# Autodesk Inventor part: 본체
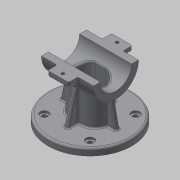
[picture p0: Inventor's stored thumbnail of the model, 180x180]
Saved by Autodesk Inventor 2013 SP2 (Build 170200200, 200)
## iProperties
Created: 2015-12
Part Number: 본체
Material: 일반
Document SubType Name: Modeling
Designer: mduedu
Density: 1 g/cm^3
Author: mduedu
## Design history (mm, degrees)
sketch "스케치1"
  geometry: L1 (45, 40)-(-45, 40); L2 (-45, 40)-(-45, -40); L3 (-45, -40)-(45, -40); L4 (45, -40)-(45, 40); L5 (45, 40)-(-45, -40); L6 (-45, 40)-(45, -40); 2 further points
  constraints: 12 end point, 2 midpoint, 2 parallel, 1 coincident, 1 horizontal, 1 perpendicular, 3 other
  dimensions: "d0" = 90 distance of L2.end L3.end; "d2" = 80 distance of L1.end L2.end
extrude "돌출1" new body sketch "스케치1" distance "d3" = 10; taper "d4" = 0 deg
sketch "스케치2"
  geometry: C1 r 32.5 at (80, 0); 1 further point
  constraints: 1 centre point
  dimensions: "d5" = 65 diameter of C1; "d116" = 80 distance of point (0, 0) C1.centre
extrude "돌출2" join sketch "스케치2" stored distance "d7" = 75; taper "d8" = 0 deg
sketch "스케치3"
  geometry: L1 (-27.5, -20)-(27.5, -20); L2 (27.5, -20)-(27.5, 20); L3 (27.5, 20)-(-27.5, 20); L4 (-27.5, 20)-(-27.5, -20); L5 (-27.5, -20)-(27.5, 20); L6 (27.5, -20)-(-27.5, 20); 1 further point
  constraints: 12 end point, 2 midpoint, 2 parallel, 1 horizontal, 1 perpendicular
  dimensions: "d9" = 55 distance of L2.end L3.end; "d11" = 40 distance of L1.end L2.end
extrude "돌출3" new body sketch "스케치3" stored distance "d12" = 75; taper "d13" = 0 deg
fillet "모깎기1"
fillet "모깎기2"
feature "결합1"
  node "솔리드2"
sketch "스케치4"
  geometry: L1 (-37.5, 47.5)-(37.5, 47.5) reference; L2 (32.5, 47.5)-(40.208, 10); L3 (37.5, 47.5)-(37.5, 112.5) reference; L4 (60.208, 0)-(60.208, 10) reference; L5 (60.208, 10)-(-60.208, 10) reference; 1 further point
  constraints: 2 end point, 2 point on line
  dimensions: "d15" = 5 distance from line of L2.start L3; "d117" = 20 distance from line of L2.end L4
sketch "스케치5"
  geometry: L1 (10, 35.208)-(56.729, 22.687); L2 (0, 60.208)-(10, 60.208) reference; L3 (10, -60.208)-(10, 60.208) reference; 2 further points
  constraints: 2 end point, 1 point on line, 2 other
  dimensions: "d118" = 25 distance from line of L1.start L2; "d119" = 75 deg angle of L1 L3
feature "리브1" dims "d19" = 1, "d20" = 6, "d21" = 0, "d22" = 0, "d23" = 1, "d24" = 1
feature "리브2" dims "d25" = 1, "d26" = 6, "d27" = 0, "d28" = 0, "d29" = 1, "d30" = 1
fillet "모깎기4" dims "d31" = 2
fillet "모깎기5" dims "d32" = 2
fillet "모깎기6" dims "d33" = 2
sketch "스케치6"
  geometry: L1 (0, 0)-(-32.88, 32.88); L2 (0, 0)-(-46.5, 0); A1 r 46.5 centre (0, 0) between (-32.88, 32.88) and (-46.5, 0); 5 further points
  constraints: 4 end point, 2 coincident, 2 point on circle, 1 centre point, 1 horizontal, 5 other
  dimensions: "d120" = 93 diameter of A1; "d122" = 45 deg angle of L1 L2; "d126" = 360 deg dimension on point (0, 0) point (-32.88, 32.88) (derived)
hole "구멍1" sketch "스케치6" at (-32.88, 32.88), (-32.88, -32.88), (32.88, -32.88), (32.88, 32.88) diameter "d34" = 7; stored, may be unused: countersink angle "d38" = 90 deg, drill point angle "d40" = 118 deg; dims "d35" = 6, "d36" = 12, "d37" = 3, "d39" = 8
fillet "모깎기13" dims "d131" = 3
hole "구멍2" diameter "d44" = 45; stored, may be unused: countersink angle "d48" = 90 deg, drill point angle "d50" = 118 deg; dims "d42" = 10, "d43" = 10, "d45" = 6, "d46" = 4, "d47" = 2, "d49" = 8
sketch "스케치7" dims "d52" = 26.5
  geometry: L1 (0, 0)-(32.5, 0); L2 (0, 0)-(22.981, 22.981); A1 r 32.5 centre (0, 0) between (32.5, 0) and (22.981, 22.981) reference; 3 further points
  constraints: 4 end point, 2 point on circle, 1 coincident, 1 horizontal, 1 point on line, 3 other
  dimensions: "d51" = 45 deg angle of L2 L1
hole "구멍3" sketch "스케치7" at (18.738, 18.738) diameter "d54" = 2.459; stored, may be unused: countersink angle "d58" = 90 deg, drill point angle "d60" = 118 deg; dims "d55" = 8, "d56" = 4, "d57" = 2, "d59" = 10
sketch "스케치8"
  geometry: L1 (72.5, 31.623)-(72.5, 46); L2 (72.5, 46)-(87.5, 46); L3 (87.5, 46)-(87.5, 31.623); A1 r 32.5 centre (80, 0) between (87.5, 31.623) and (72.5, 31.623) reference; 2 further points
  constraints: 6 end point, 2 point on circle, 1 horizontal, 1 midpoint, 1 parallel, 1 vertical, 1 vertical alignment
  dimensions: "d64" = 15 distance of L1.end L2.end; "d66" = 46 distance from line of L2 A1.centre
extrude "돌출4" join sketch "스케치8" stored distance "d67" = 30; taper "d68" = 0 deg
fillet "모깎기8" dims "d69" = 3
fillet "모깎기9" dims "d70" = 2
node "작업 평면2"
sketch "스케치16"
  geometry: L1 (33.166, 72.5)-(44, 72.5) reference; L2 (42.5, 72.5)-(28.53, 64.434); L3 (46, 75.5)-(46, 84.5) reference; 2 further points
  constraints: 2 end point, 1 point on line, 2 other
  dimensions: "d138" = 30 deg angle of L2 L1; "d139" = 3.5 distance from line of L2.start L3
feature "리브3" sketch "스케치16" dims "d140" = 1, "d141" = 3, "d142" = 0, "d143" = 0, "d144" = 1, "d145" = 1
fillet "모깎기14" dims "d146" = 1
fillet "모깎기15" dims "d147" = 1
sketch "스케치9"
  geometry: L1 (-76, 82.5)-(76, 82.5); L2 (76, 82.5)-(76, 0); L3 (76, 0)-(-76, 0); L4 (-76, 0)-(-76, 82.5); L5 (-46, 4.5)-(-46, -4.5) reference; C1 r 32.5 at (0, 0) reference; 2 further points
  constraints: 8 end point, 2 parallel, 1 coincident, 1 horizontal, 1 midpoint, 1 perpendicular
  dimensions: "d71" = 50 distance edge to line of C1 L1; "d72" = 30 distance between parallel lines of L4 L5
extrude "돌출5" cut sketch "스케치9" stored distance "d73" = 0; taper "d74" = 0 deg
node "작업 평면1"
sketch "스케치10"
  geometry: L1 (-7.5, 15)-(7.5, 15); L2 (-7.5, -15)-(7.5, -15); A1 r 20 centre (-7.5, 0) between (-7.5, 20) and (-26.977, 4.545) reference; A2 r 20 centre (7.5, 0) between (26.977, 4.545) and (7.5, 20) reference; A3 r 15 centre (-7.5, 0) between (-7.5, 15) and (-7.5, -15); A4 r 15 centre (7.5, 0) between (7.5, -15) and (7.5, 15); 1 further point
  constraints: 7 point on circle, 4 end point, 4 tangent, 3 point on line, 2 centre point, 2 coincident, 1 horizontal
  dimensions: "d77" = 5 radial gap between concentric circles of A3 A1
extrude "돌출6" cut sketch "스케치10" stored distance "d78" = 50; taper "d79" = 0 deg
fillet "모깎기10" dims "d80" = 3
sketch "스케치11"
  geometry: 2 further points
  constraints: 1 coincident
hole "구멍4" sketch "스케치11" at (0, 0) diameter "d81" = 12; stored, may be unused: countersink angle "d85" = 90 deg, drill point angle "d87" = 118 deg; dims "d82" = 8, "d83" = 40, "d84" = 10, "d86" = 10
sketch "스케치12"
  geometry: C1 r 10 at (0, 0); 1 further point
  constraints: 1 centre point, 1 coincident
  dimensions: "d88" = 20 diameter of C1
extrude "돌출7" cut sketch "스케치12" distance "d89" = 5; taper "d90" = 0 deg
chamfer "모따기1" distance "d91" = 1; stored, may be unused: second distance "d92" = 2, angle "d93" = 45 deg
fillet "모깎기11" dims "d94" = 0.5
sketch "스케치13"
  geometry: L1 (-3, 10.834)-(-3, 1.039) reference; L2 (27, 1.039)-(27, 10.834) reference; L3 (-3, 5.936)-(27, 5.936); L4 (24, 12.834)-(0, 12.834) reference; L5 (12, 12.834)-(12, -33.166); 1 further point
  constraints: 4 end point, 4 midpoint, 1 perpendicular, 1 point on line
hole "구멍5" sketch "스케치13" at (12, 5.936) diameter "d101" = 4.5; stored, may be unused: countersink angle "d105" = 90 deg, drill point angle "d107" = 0 deg; dims "d102" = 6, "d103" = 4, "d104" = 2, "d106" = 8
fillet "모깎기12" dims "d115" = 0.3
node "솔리드1"
mirror "대칭1"
mirror "대칭2"
pattern_circular "원형 패턴1" dims angle "d62" = 360 deg
mirror "대칭3"
mirror "대칭7"
mirror "대칭4"
mirror "대칭6"
other parameters: "d137" = -5
